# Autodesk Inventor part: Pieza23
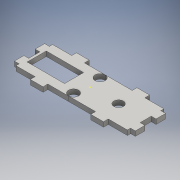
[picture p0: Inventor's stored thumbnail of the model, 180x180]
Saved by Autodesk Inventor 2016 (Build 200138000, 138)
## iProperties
Created: 2016-06
Part Number: Pieza23
Material: Genérico
Document SubType Name: Modeling
Designer: adm
Density: 1 g/cm^3
Appearance: Valor por defecto
Author: adm
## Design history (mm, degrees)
sketch "Boceto1"
  geometry: L1 (-15, -11.5)-(-15, -14.5); L2 (-23, -11.5)-(-23, -14.5); L3 (-23, -14.5)-(-15, -14.5); L4 (-15, -11.5)-(-23, -11.5); L5 (-23, 11.5)-(-15, 11.5); L6 (-15, 14.5)-(-23, 14.5); L7 (-15, 14.5)-(-15, 11.5); L8 (-40, -16.5)-(-40, 16.5); L9 (-35, -9.5)-(-35, -3.5); L10 (-35, 3.5)-(-35, 9.5); L11 (-23, 14.5)-(-23, 11.5); L12 (35, -3.5)-(35, -9.5); L13 (35, 9.5)-(35, 3.5); L14 (35, -9.5)-(38, -9.5); L15 (38, -9.5)-(38, -3.5); L16 (35, -3.5)-(38, -3.5); L17 (35, 9.5)-(38, 9.5); L18 (38, 3.5)-(38, 9.5); L19 (35, 3.5)-(38, 3.5); L20 (-38, 9.5)-(-35, 9.5); L21 (-38, 9.5)-(-38, 3.5); L22 (-38, 3.5)-(-35, 3.5); L23 (-38, -3.5)-(-35, -3.5); L24 (-38, -3.5)-(-38, -9.5); L25 (-38, -9.5)-(-35, -9.5); L26 (35, -11.5)-(-35, 11.5); L27 (-35, -11.5)-(28.913, 9.5); L28 (-40, 16.5)-(40, 16.5); L29 (40, -16.5)-(-40, -16.5); L30 (15, -11.5)-(15, -14.5); L31 (15, 14.5)-(15, 11.5); L32 (15, 11.5)-(23, 11.5); L33 (23, 14.5)-(23, 11.5); L34 (23, 14.5)-(15, 14.5); L35 (23, -11.5)-(23, -14.5); L36 (15, -14.5)-(23, -14.5); L37 (40, 16.5)-(40, -16.5); L38 (23, -11.5)-(15, -11.5); L39 (-35, -11.5)-(35, -11.5); L40 (35, -11.5)-(35, 11.5); L41 (35, 11.5)-(-35, 11.5); L42 (-35, 11.5)-(-35, -11.5); L43 (-35, -11.5)-(35, 11.5); L44 (35, -11.5)-(-35, 11.5); 2 further points
  constraints: 88 end point, 20 parallel, 11 horizontal, 10 perpendicular, 8 vertical, 3 midpoint, 2 horizontal alignment, 1 point on line
  dimensions: "d0" = 70 distance of L26.start L27.start; "d1" = 6 distance of L10.start L10.end; "d2" = 7 distance between parallel lines of L28 L20; "d3" = 6 distance of L18.start L17.end; "d4" = 33 distance between parallel lines of L29 L28; "d5" = 7 distance between parallel lines of L22 L23; "d6" = 7 distance between parallel lines of L29 L25; "d34" = 70 distance of L40.end L41.end
extrude "Extrusión1" new body sketch "Boceto1" distance "d7" = 3; taper "d8" = 0 deg
sketch "Boceto2"
  geometry: L1 (15, -11.5)-(23, -11.5); L2 (-10, -6)-(-10, 6); L3 (-15, -11.5)-(-15, -14.5); L4 (-33.5, -6)-(-10, -6); L5 (-33.5, 6)-(-33.5, -6); L6 (-10, 6)-(-33.5, 6); L7 (35, 3.5)-(35, 9.5); L8 (35, -3.5)-(35, -9.5); L9 (35, -11.5)-(35, 11.5) reference; L10 (35, 11.5)-(-35, 11.5) reference; L11 (-35, -11.5)-(35, -11.5) reference; C1 r 3.175 at (-2, -8.325); C2 r 3 at (18, 0); C3 r 3.175 at (-2, 8.325); 3 further points
  constraints: 16 end point, 3 centre point, 2 parallel, 2 tangent, 1 horizontal, 1 horizontal alignment, 1 midpoint, 1 perpendicular
  dimensions: "d10" = 6 diameter of C2; "d13" = 6.35 diameter of C3; "d14" = 6.35 diameter of C1; "d15" = 23.5 distance of L4.start L2.start; "d16" = 12 distance of L2.start L2.end; "d17" = 8 distance from line of C3.centre L2; "d36" = 17 distance from line of L9 C2.centre; "d37" = 20 horizontal distance of C2.centre C1.centre; "d38" = 20 horizontal distance of C2.centre C3.centre
extrude "Extrusión2" cut sketch "Boceto2" distance "d18" = 3; taper "d19" = 0 deg
sketch "Boceto3"
  geometry: L1 (35, 9.5)-(38, 9.5); L2 (38, 9.5)-(38, 3.5); L3 (38, 3.5)-(35, 3.5); L4 (35, 3.5)-(35, 9.5); L5 (35, -3.5)-(38, -3.5); L6 (38, -3.5)-(38, -9.5); L7 (38, -9.5)-(35, -9.5); L8 (35, -9.5)-(35, -3.5); L9 (-2, -11.5)-(35, -11.5) reference; L10 (35, 11.5)-(-35, 11.5) reference; L11 (0, 0)-(0, -19); L12 (-35, 9.5)-(-38, 9.5); L13 (-38, 9.5)-(-38, 3.5); L14 (-38, 3.5)-(-35, 3.5); L15 (-35, -3.5)-(-38, -3.5); L16 (-38, -3.5)-(-38, -9.5); L17 (-38, -9.5)-(-35, -9.5); L18 (-35, 9.5)-(-35, 3.5); L19 (-35, 11.5)-(-35, -11.5) reference; L20 (-35, -3.5)-(-35, -9.5); 2 further points
  constraints: 34 end point, 8 symmetric about line, 4 parallel, 3 perpendicular, 2 horizontal, 2 vertical alignment, 1 collinear, 1 vertical
  dimensions: "d20" = 6 distance of L5.end L6.end; "d21" = 6 distance of L1.end L2.end; "d22" = 3 distance of L2.end L3.end; "d23" = 3 distance of L5.start L5.end; "d24" = 7 distance between parallel lines of L5 L3; "d25" = 2 distance between parallel lines of L9 L7; "d26" = 2 distance between parallel lines of L10 L1 (derived)
extrude "Extrusión3" join sketch "Boceto3" distance "d27" = 3; taper "d28" = 0 deg
sketch "Boceto4"
  geometry: L1 (-2, -11.5)-(35, -11.5) reference; L2 (23, -11.5)-(15, -11.5); L3 (15, -11.5)-(15, -14.5); L4 (15, -14.5)-(23, -14.5); L5 (23, -14.5)-(23, -11.5); L6 (35, -11.5)-(35, -9.5) reference; L7 (0, 0)-(0, -20); L8 (0, 0)-(10, 0); L9 (-7.04, -11.5)-(-35, -11.5); L10 (-23, -11.5)-(-15, -11.5); L11 (-15, -11.5)-(-15, -14.5); L12 (-15, -14.5)-(-23, -14.5); L13 (-23, -14.5)-(-23, -11.5); L14 (7.04, 11.5)-(35, 11.5); L15 (23, 11.5)-(15, 11.5); L16 (15, 11.5)-(15, 14.5); L17 (15, 14.5)-(23, 14.5); L18 (23, 14.5)-(23, 11.5); L19 (0, 0)-(0, 20); L20 (-7.04, 11.5)-(-35, 11.5); L21 (-23, 11.5)-(-15, 11.5); L22 (-15, 11.5)-(-15, 14.5); L23 (-15, 14.5)-(-23, 14.5); L24 (-23, 14.5)-(-23, 11.5); 1 further point
  constraints: 44 end point, 19 symmetric about line, 4 point on line, 2 parallel, 1 horizontal, 1 perpendicular, 1 vertical
  dimensions: "d29" = 8 distance of L3.end L4.end; "d31" = 3 distance of L2.end L3.end; "d35" = 15 distance between parallel lines of L7 L3
extrude "Extrusión4" join sketch "Boceto4" distance "d32" = 3; taper "d33" = 0 deg
sketch "Boceto5"
  geometry: 1 further point
node "Sólido1"
